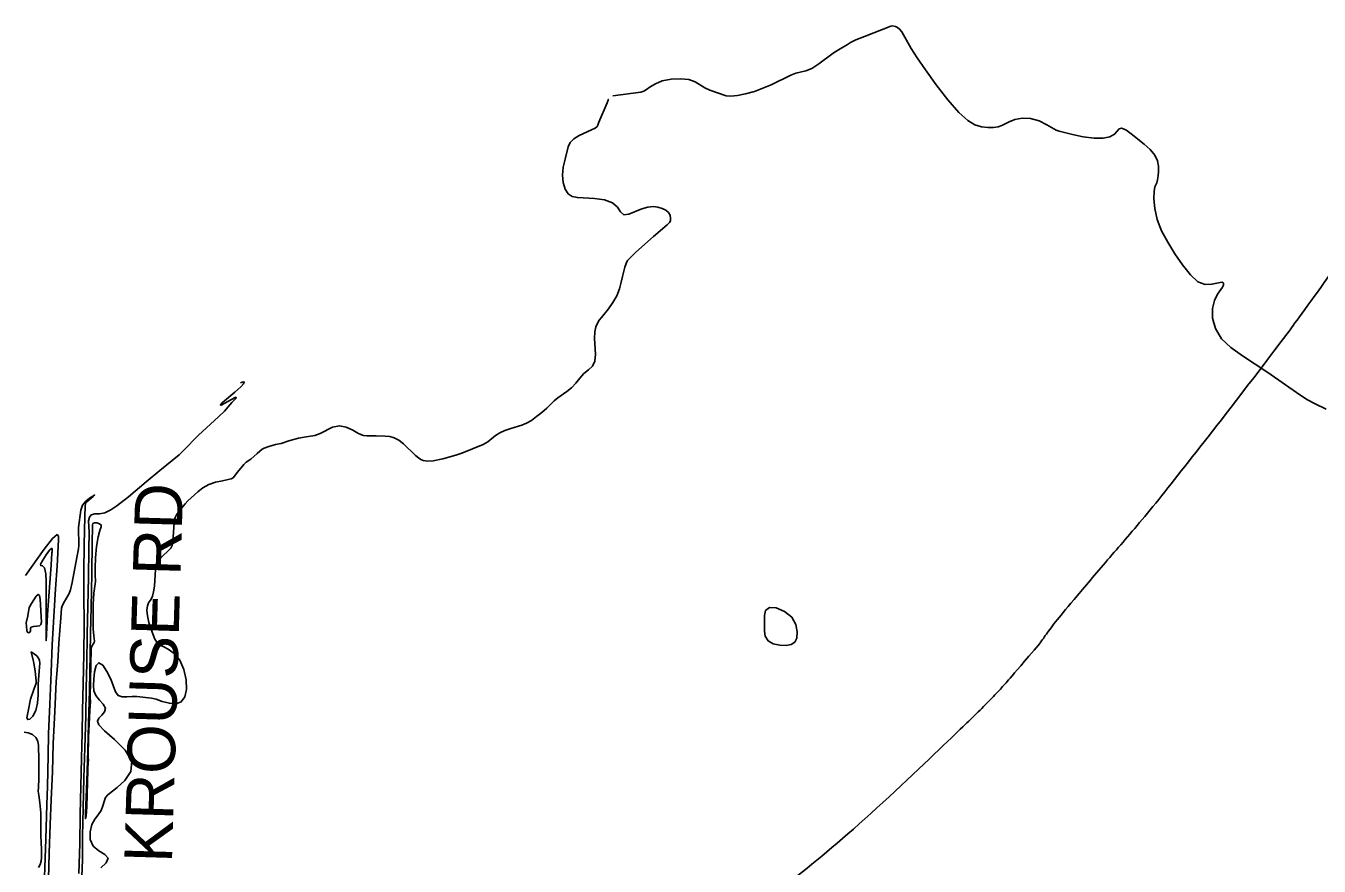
# Model space of a CAD drawing. Extents: x -468541894 to 3393103, y -306086142 to 1227927.
# Drawn here: x 1845797 to 1847065, y 539346 to 540170 of the extents above; entities that cross this region are included whole.
import ezdxf

# ---------------------------------------------------------------- set-up
doc = ezdxf.new("R2010")
doc.units = 0
for name, color, linetype in [('DT_X_Contour_Minor', 7, 'Continuous'), ('Level 25', 7, 'Continuous'), ('Level 40', 7, 'Continuous')]:
    doc.layers.add(name, color=color, linetype=linetype)

msp = doc.modelspace()

# ---------------------------------------------------------------- linework, layer by layer
at = {"layer": 'DT_X_Contour_Minor'}
for points in [[(1846372.3, 540101.8), (1846400, 540105.4), (1846402.8, 540106.3), (1846405.5, 540107.9), (1846409.1, 540110.5), (1846414.1, 540113.6), (1846420.9, 540116.4), (1846429.5, 540118.1), (1846438.7, 540118.6), (1846447, 540117.7), (1846453.3, 540115.4), (1846462.7, 540109.5), (1846467.6, 540107.2), (1846483.7, 540101.9), (1846488.2, 540101.5), (1846494.7, 540102.2), (1846502.7, 540103.7), (1846511.3, 540106.1), (1846519.7, 540109.2), (1846527.6, 540112.7), (1846547, 540122.2), (1846552.1, 540124.1), (1846561.8, 540126.3), (1846567.6, 540128.7), (1846574.6, 540133.1), (1846588.7, 540143.5), (1846593.9, 540146.9), (1846602.6, 540152), (1846605.7, 540154), (1846610.9, 540156.6), (1846619.2, 540160.1), (1846645.1, 540170.2), (1846646.7, 540170.4), (1846649.7, 540169.8), (1846651.7, 540168.9), (1846653.8, 540167.2), (1846655.8, 540164.5), (1846665.1, 540148.2), (1846670.9, 540139.1), (1846679.1, 540127.2), (1846689.6, 540112.7), (1846701.1, 540097.8), (1846711.9, 540085.4), (1846720.7, 540077.5), (1846727.7, 540073.3), (1846734, 540071.5), (1846740.2, 540070.8), (1846745.9, 540070.8), (1846750.5, 540071.4), (1846754, 540072.7), (1846761.1, 540076.4), (1846766.8, 540078.5), (1846774, 540080), (1846782.2, 540079.7), (1846790.6, 540077.2), (1846798.3, 540073.5), (1846807.5, 540068.2), (1846810.4, 540067), (1846823.5, 540063.8), (1846834, 540061.7), (1846844.6, 540060.3), (1846853.4, 540060.3), (1846860.1, 540061.7), (1846864.6, 540064.1), (1846869.2, 540069.3), (1846871.6, 540070), (1846875.6, 540068.3), (1846881, 540064.6), (1846893.6, 540054.5), (1846899.6, 540049.1), (1846904.2, 540043.5), (1846906.7, 540038), (1846907.7, 540032.7), (1846907.8, 540027.7), (1846907.5, 540023.2), (1846906.9, 540019.4), (1846906.2, 540016.6), (1846904.3, 540012.4), (1846903.5, 540008.1), (1846903.2, 540000.8), (1846904, 539991.2), (1846906.3, 539980.4), (1846910.8, 539969.3), (1846916.9, 539958.2), (1846923.9, 539947), (1846931.4, 539935.9), (1846939, 539926.2), (1846946.5, 539919.5), (1846953.7, 539916.9), (1846960.2, 539917), (1846968.4, 539918.8), (1846970.2, 539918.9), (1846971.1, 539918.5), (1846971.5, 539917.9), (1846971.6, 539916.4), (1846971.3, 539915.6), (1846970.5, 539914.1), (1846965.8, 539907.2), (1846962.8, 539901.1), (1846960.7, 539893.3), (1846960.8, 539883.8)], [(1846367.5, 540097.8), (1846368, 540098.2), (1846367.9, 540097.4), (1846366.9, 540094.9), (1846358.6, 540075.8), (1846357.7, 540072.9), (1846356.9, 540071.7), (1846355, 540070.2), (1846351.4, 540068.3), (1846339.5, 540062.9), (1846334, 540059.6), (1846330.6, 540056.1), (1846328.7, 540051.8), (1846325.5, 540039.6), (1846323.8, 540031.9), (1846323, 540024), (1846323.7, 540016.7), (1846325.7, 540010.4), (1846328.7, 540005.8), (1846332.5, 540003.2), (1846337.7, 540002), (1846354.3, 540001), (1846364.1, 539999.7), (1846372.2, 539996.9), (1846377, 539992.5), (1846379.9, 539987.9), (1846383.1, 539985.2), (1846388.1, 539985.7), (1846401, 539991.1), (1846406.9, 539992.7), (1846412.1, 539993.1), (1846416.7, 539992.5), (1846420.8, 539991.4), (1846424.3, 539989.7), (1846426.9, 539987.4), (1846428.5, 539984.6), (1846429.1, 539981.7), (1846429, 539979.3), (1846428.1, 539977.5), (1846425.6, 539975.2), (1846412.4, 539964), (1846395, 539948.4), (1846389.8, 539943.4), (1846386.9, 539940.2), (1846385.4, 539937.4), (1846384.1, 539933.9), (1846381.9, 539924.7), (1846380.6, 539918.9), (1846378.8, 539912.5), (1846376.2, 539905.8), (1846372.5, 539899.2), (1846368.2, 539893), (1846361.3, 539884.5), (1846359, 539881.8), (1846357.2, 539878.9), (1846355.7, 539875.1), (1846354.7, 539870.2), (1846354.4, 539863.8), (1846355.4, 539848.3), (1846354.8, 539841.5), (1846352.3, 539836.7), (1846348.4, 539833.1), (1846344.1, 539829.4), (1846340, 539824.9), (1846336.1, 539820), (1846332, 539815.4), (1846327.4, 539811.7), (1846318.5, 539805.8), (1846314.8, 539802.7), (1846307.5, 539795.5), (1846302.8, 539791.3), (1846297.6, 539787.2), (1846292.5, 539783.5), (1846287.7, 539780.8), (1846283, 539778.8), (1846272.3, 539775.5), (1846266.5, 539773.7), (1846261.4, 539771.4), (1846257.3, 539768.6), (1846249.9, 539762.5), (1846245.2, 539760), (1846234.7, 539755.5), (1846224.2, 539751.4), (1846218.4, 539749.4), (1846205.5, 539745.9), (1846196, 539743.9), (1846191, 539743.6), (1846188.7, 539743.8), (1846186.4, 539744.3), (1846184, 539745.3), (1846181.6, 539746.8), (1846178.8, 539749.1), (1846167, 539760.6), (1846162.3, 539764.1), (1846157.9, 539766.4), (1846153.5, 539767.7), (1846149, 539768.2), (1846140.1, 539768.4), (1846131.1, 539768.5), (1846127.8, 539768.7), (1846125.7, 539769.3)], [(1846960.8, 539883.8), (1846963.6, 539873.5), (1846969.4, 539863.6), (1846978.6, 539854.9), (1846990.1, 539846.8), (1847002.6, 539838.8), (1847015.1, 539830.4), (1847046.4, 539808.6), (1847054, 539803.8), (1847060.7, 539800.1), (1847072.4, 539794.6)], [(1845850.9, 539319.5), (1845852, 539352.7), (1845852.2, 539375.8), (1845852.6, 539403.3), (1845853.5, 539432.9), (1845854.3, 539462.5), (1845855.2, 539493.5), (1845855.8, 539521.1), (1845856.3, 539545.5), (1845856.8, 539573.5), (1845857.3, 539601.5), (1845857.9, 539629.9), (1845858.3, 539657.1), (1845858.6, 539673.9), (1845858.1, 539685), (1845858.9, 539688.5), (1845860.7, 539690.9), (1845864.1, 539691.8), (1845868.7, 539692), (1845874.1, 539692.9), (1845879.9, 539695.7), (1845885.8, 539699.7), (1845897.1, 539708.7), (1845914.5, 539723.3), (1845928, 539734.5), (1845946.9, 539749.8), (1845951.3, 539754), (1845965.8, 539768.9), (1845985.5, 539787.1), (1845991.3, 539792.7), (1845996.7, 539798.7), (1845998.5, 539800.9), (1846003.1, 539805.8), (1846002.5, 539806.2), (1845998.3, 539804), (1845988.1, 539798.4), (1845987.4, 539798.7), (1845989.6, 539801), (1846001.5, 539811.2), (1846007.3, 539816.4), (1846010, 539819.5), (1846010.8, 539821.2), (1846010.5, 539821.4), (1846008.6, 539820.9), (1846007, 539820.2)], [(1846125.7, 539769.3), (1846122.3, 539771), (1846117.2, 539774), (1846110.9, 539777), (1846104.1, 539778.3), (1846097.4, 539776.9), (1846085.3, 539770.7), (1846080, 539768.8), (1846069.7, 539767.1), (1846064, 539766.1), (1846054.4, 539763.5), (1846047.1, 539760.8), (1846041.5, 539759.8), (1846034.9, 539758), (1846030.2, 539756.4), (1846028.5, 539755.4), (1846023.5, 539751.1), (1846017.1, 539745.5), (1846012.8, 539742.4), (1846010.5, 539740.2), (1846004.2, 539732.7), (1845999.8, 539727.1), (1845998, 539726.1), (1845994.9, 539725.4), (1845989.5, 539724.4), (1845982.7, 539722.8), (1845975.9, 539720.5), (1845970.1, 539717.3), (1845965.3, 539713.6), (1845955.4, 539704.5), (1845952.8, 539701.8), (1845947.9, 539695.8), (1845944.3, 539690.9), (1845943.2, 539688.9), (1845942.4, 539686.6), (1845941.9, 539683.5), (1845940.9, 539669), (1845940.7, 539663.4), (1845940.2, 539661), (1845938.7, 539658.3), (1845935.9, 539655.3), (1845926.7, 539646.8), (1845925.1, 539644.3), (1845924.1, 539641.2), (1845923.6, 539637.2), (1845922.6, 539621), (1845921.8, 539615.4), (1845920.8, 539611), (1845919.6, 539608.3), (1845916.9, 539604.5), (1845915.8, 539601.6), (1845915.3, 539597.5), (1845915.7, 539592), (1845917.2, 539585.3), (1845919.3, 539578.4), (1845923.2, 539568.9), (1845925.9, 539564.3), (1845926.8, 539563.6), (1845931.1, 539561.8), (1845936.1, 539559.3), (1845942, 539555), (1845947.6, 539548.4), (1845951.6, 539539.3), (1845953.7, 539529.2), (1845954, 539519.7), (1845952.4, 539512.4), (1845949, 539507.7), (1845943.9, 539505.6), (1845937.3, 539506.1), (1845930.4, 539508), (1845924.3, 539510), (1845919.9, 539511.1), (1845905.5, 539512.8), (1845900.7, 539512.9), (1845895.7, 539512.5), (1845890.9, 539512.3), (1845887, 539513.6), (1845884.5, 539517.2), (1845879.9, 539529.7), (1845876.1, 539537.2), (1845871.9, 539543.4), (1845868.1, 539545.9), (1845865.5, 539543.2), (1845864, 539537.1), (1845863.1, 539529.9), (1845862.8, 539523.6), (1845863.3, 539518.3), (1845865.2, 539513.6), (1845868.8, 539509.3), (1845872.5, 539505.2), (1845874.5, 539501.4), (1845873.7, 539497.8), (1845871, 539494.5), (1845868.2, 539491.5), (1845866.8, 539488.7), (1845868.2, 539485), (1845873.7, 539479.2), (1845883.6, 539470.7), (1845894.1, 539460.3), (1845900.6, 539449.3), (1845899.6, 539439.1)], [(1845818.6, 539334), (1845819.4, 539359.1), (1845820.3, 539387.3), (1845821.3, 539411.4), (1845822.6, 539438.9), (1845823.4, 539466.8), (1845824.8, 539498.2), (1845826.4, 539527.4), (1845827.8, 539546.9), (1845828.9, 539565.1), (1845830.7, 539590), (1845831.5, 539599.3), (1845832, 539601.2), (1845833.1, 539603.6), (1845839.1, 539613.8), (1845840.4, 539617.5), (1845841.8, 539624.7), (1845846.5, 539649), (1845848.2, 539657.7), (1845848.5, 539661), (1845848.2, 539678.5), (1845850.4, 539695.4), (1845852.2, 539700.3), (1845855.3, 539704.3), (1845858.9, 539707.3), (1845863.9, 539710.3), (1845862.6, 539709), (1845856.5, 539703.7), (1845855.4, 539703.1), (1845855.1, 539702.1), (1845854.8, 539699.5), (1845854.3, 539689.3), (1845853.8, 539661.6), (1845853.4, 539634.9), (1845853.3, 539612.8), (1845853.6, 539583.6), (1845853.3, 539554.1), (1845852.6, 539525.5), (1845852, 539498.7), (1845851.7, 539477.3), (1845851, 539452), (1845850.5, 539424.9), (1845849.9, 539397.2), (1845849.4, 539368.3), (1845848.6, 539339.2)], [(1845796.1, 539631.5), (1845814.6, 539657.1), (1845822.7, 539667.7), (1845827.1, 539671.5), (1845828.6, 539670.1), (1845828.6, 539666.3), (1845827.1, 539640.6), (1845825.6, 539618.4), (1845823.8, 539591.3), (1845822.3, 539563.4), (1845821.5, 539536.7), (1845820.2, 539505.2), (1845818.8, 539476.1), (1845818.5, 539455), (1845817.9, 539424.5), (1845817.2, 539407), (1845816, 539372.8), (1845815.2, 539345), (1845814.3, 539317.6), (1845813.1, 539283.3), (1845812.5, 539261.9), (1845811.7, 539224.5), (1845811.3, 539214.9)], [(1845860.7, 539559.7), (1845859.8, 539528.2), (1845859.7, 539511.4), (1845859.9, 539508), (1845859.2, 539498.6), (1845858.1, 539472.5), (1845857.8, 539453.6), (1845858, 539449.6), (1845857.6, 539449), (1845857.2, 539440.4), (1845856.3, 539404.7), (1845855.7, 539395.6), (1845855, 539392.9), (1845855.1, 539398.7), (1845856.2, 539429.7), (1845857.2, 539460.2), (1845858.1, 539486.6), (1845859, 539518.8), (1845859.7, 539554.6), (1845860.1, 539575), (1845860.6, 539600.4), (1845861.3, 539633.1), (1845861.7, 539664), (1845861.8, 539678.8), (1845861.8, 539681.1), (1845862.3, 539682.3), (1845863.8, 539683.1), (1845866.2, 539683.1), (1845868.8, 539682.2), (1845870.5, 539680.9), (1845870.4, 539679), (1845869.2, 539675.6), (1845867.4, 539669.4), (1845865.9, 539659.9), (1845864.9, 539648.9), (1845864.4, 539639.1), (1845864.4, 539632.2), (1845864.9, 539625.6), (1845863.3, 539614.2), (1845862.7, 539603.3), (1845862.4, 539590.4), (1845862.5, 539579.1), (1845863.1, 539572.2), (1845864, 539566.9), (1845863.6, 539565.7), (1845861.2, 539562.1), (1845860.7, 539559.7)], [(1845822.1, 539653.5), (1845821.3, 539641.7), (1845818.9, 539611.2), (1845817.8, 539592.7), (1845816.6, 539567.5), (1845816.3, 539567.5), (1845816.3, 539571.7), (1845816.5, 539592.5), (1845816.4, 539610.9), (1845816.3, 539618.8), (1845816.3, 539625.6), (1845816, 539633.1), (1845814.9, 539638.8), (1845812.9, 539640.9), (1845811.2, 539641.2), (1845811, 539642.4), (1845813.1, 539646.4), (1845816.6, 539651.7), (1845819.8, 539656.1), (1845821.7, 539657.9), (1845822.3, 539657.8), (1845822.2, 539654.6), (1845822.1, 539653.5)], [(1845796.9, 539585), (1845798.4, 539591.8), (1845799.9, 539600), (1845802, 539604), (1845804.2, 539607.5), (1845806.6, 539611), (1845808.7, 539612.8), (1845809.9, 539611.7), (1845810.5, 539608.3), (1845811.8, 539585.6), (1845811.3, 539583.5), (1845809.8, 539582.2), (1845807.1, 539581.6), (1845804.1, 539581.3), (1845801.8, 539580.8), (1845801, 539579.7), (1845801, 539576.9), (1845800.4, 539575.7), (1845799.3, 539575.2), (1845798.2, 539575.7), (1845797.5, 539577.3), (1845797, 539581.7), (1845796.9, 539585)], [(1846521.1, 539584.1), (1846521.1, 539592.2), (1846522.3, 539597), (1846526, 539600), (1846532.7, 539599.6), (1846540.8, 539596.1), (1846547.9, 539590.4), (1846552, 539583.4), (1846553.4, 539576.2), (1846552.9, 539570.1), (1846550.8, 539566), (1846547.4, 539563.8), (1846542.5, 539562.9), (1846536.3, 539563), (1846529.8, 539564.4), (1846524.7, 539567.3), (1846522, 539571.8), (1846521.1, 539576.7), (1846521.1, 539584.1)], [(1845801.7, 539556.6), (1845805, 539554.4), (1845807.2, 539552.6), (1845809, 539550.5), (1845810, 539548.2), (1845810.3, 539545.5), (1845809.7, 539537.5), (1845808.7, 539524.7), (1845808.5, 539514.3), (1845807.8, 539506.3), (1845806.2, 539498.9), (1845803.5, 539493.5), (1845800.5, 539490.6), (1845798.3, 539490.1), (1845797.6, 539491.7), (1845798.9, 539498.5), (1845801, 539510.3), (1845804.3, 539519.7), (1845806.6, 539526), (1845806.7, 539527.9), (1845805.6, 539537.8), (1845803.9, 539547.1), (1845801.7, 539556.6)], [(1845809, 539345.1), (1845810.6, 539347.9), (1845811.5, 539351.3), (1845811.8, 539355), (1845811.7, 539362.8), (1845811.3, 539376.4), (1845811.1, 539398.7), (1845810.3, 539408.4), (1845809.4, 539415.9), (1845808.7, 539419.8), (1845808.8, 539423.5), (1845809.2, 539432.4), (1845809.3, 539450.8), (1845808.9, 539464.6), (1845808.2, 539468.9), (1845806.3, 539472.6), (1845803, 539475.4), (1845798.8, 539477.2), (1845795, 539477.8)], [(1845899.6, 539439.1), (1845893.6, 539430.3), (1845886.2, 539423.6), (1845876.8, 539416.5), (1845874.6, 539413.7), (1845873.3, 539409.9), (1845872.2, 539405.4), (1845870.5, 539400.9), (1845867.6, 539396.8), (1845864.3, 539392.5), (1845861.2, 539387.2), (1845859.5, 539380.2), (1845859.7, 539372.7), (1845862.6, 539366.1), (1845868.2, 539361.4), (1845874.1, 539357.9), (1845877.2, 539354.2), (1845875.3, 539349.6), (1845870.2, 539344.7)]]:
    msp.add_lwpolyline(points, dxfattribs=at)
at = {"layer": 'Level 25'}
for points in [[(1847193.8, 540107.2), (1847164.9, 540060.6), (1847128.1, 540002.4), (1847077.9, 539928.5), (1847040.3, 539877.2), (1847035.8, 539871.1)], [(1847035.8, 539871.1), (1846993.9, 539815.4), (1846944.5, 539752.2), (1846894.2, 539688.2), (1846860, 539649.6), (1846825.4, 539608.4), (1846806.8, 539586.5), (1846797.4, 539573.5), (1846792.5, 539566.5), (1846791.2, 539564.7)], [(1846791.2, 539564.7), (1846759.6, 539527.7), (1846755.7, 539523.5), (1846744.7, 539511.5), (1846731.1, 539497.8), (1846716, 539483.2), (1846608.4, 539380.3), (1846534.8, 539322.2), (1846471.7, 539269), (1846358.6, 539175.5), (1846294.4, 539133.1), (1846222, 539082.3), (1846185.1, 539062.3), (1846148.5, 539041.1), (1846113.2, 539021.9), (1846084.1, 539006.6)], [(1846008.2, 538965.4), (1845992.4, 538957.1), (1845964.3, 538943.2), (1845947.7, 538933.6), (1845945.5, 538932.2), (1845945.2, 538931.3), (1845945, 538929.9), (1845948.8, 538924.1), (1845950, 538922.5), (1845950.9, 538922.6), (1845954.4, 538923), (1845989.4, 538939.7), (1846036.7, 538963.5), (1846075.9, 538982.1), (1846133, 539002.3), (1846233.4, 539037.1), (1846256, 539044.4), (1847268.1, 539377.4)]]:
    msp.add_open_spline(points, degree=3, dxfattribs=at)

# ---------------------------------------------------------------- texts
at = {"layer": 'Level 40'}
msp.add_text('KROUSE RD', height=46.8, rotation=88.2904, dxfattribs=at).set_placement((1845939.8, 539349.3))

doc.saveas('drawing.dxf')
